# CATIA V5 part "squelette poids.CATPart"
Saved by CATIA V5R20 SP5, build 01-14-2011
Part number: squelette poids
Publications: "Point.3", "Point.1", "rayon du poids"
Bounding box of the stored display mesh (mm): x 0 to 20, y 101.557 to 101.557, z -77.703 to 172.297
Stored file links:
  F:\projet\yyang_IAO\squelette poids.CATPart
  F:\projet\yyang_IAO\iao.CATProduct
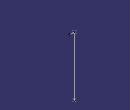
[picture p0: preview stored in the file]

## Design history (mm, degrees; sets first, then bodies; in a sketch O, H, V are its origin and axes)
Parameters
  `distance de centre du poids` = 250 mm
  `rayon du poids` = 50 mm
Set1
  Point1: linked copy from another document
  Plane1: linked copy from another document
Body1 (main body)
  Point2: (0, 0, 0), relative to Point1
  Line1: type PtDir, RefPoint Point1, Direction (0, 0, 1), Start 0, End 250 {= `distance de centre du poids`}
  Plane2: type Offset, RefPlane Plane1, Offset 0
  Line2: type PtDir, RefPoint Point1, Direction (1, 0, 0), Start 0, End 20
  Point3: (0, 0, 0), relative to vertex of Line1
